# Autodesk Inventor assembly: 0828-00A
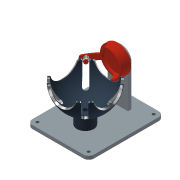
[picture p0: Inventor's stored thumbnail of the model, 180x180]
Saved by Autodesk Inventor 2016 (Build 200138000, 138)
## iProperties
Shininess: 64.0
Length Units: 11269
Angle Units: 11279
Time Units: 11290
Mass Units: 11283
Length Display Precision: 3
Angle Display Precision: 2
Compacted: True
Created: 2003-08
Part Number: 0828-00A
Document SubType Name: Assembly
Designer: 40664
Manufacturer: Standard
Standards Organization: Custom
Density: 0.0
Volumn: 0.0
Area: 0.0
PropertySet Name: Model Information
Control State: 0
Master: False
Checked Out: False
Author: 40664
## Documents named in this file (7)
- G:\InventorKurs\Geneva2\0828-00A.iam
- G:\InventorKurs\Geneva2\Geneva.ipt
- G:\InventorKurs\Geneva2\Plate.ipt
- G:\InventorKurs\Geneva2\0828-01P.ipt
- G:\InventorKurs\Geneva2\0828-02P.ipt
- G:\InventorKurs\Geneva2\Pin.ipt
- G:\InventorKurs\Geneva2\DIN471.ipt
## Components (6 placed, 6 different names)
1. Plate:1 — Flush:1, Insert:1, Mate:1, Mate:2, Flush:2, Angle:1, Angle:5
2. Geneva:1 — Insert:1, Angle:1
3. 0828-01P:1 — Mate:1, Mate:2, Insert:2, Flush:2
4. 0828-02P:1 — Insert:2, Insert:3, Angle:5
5. DIN 471  <= 9mm 8 x 0.8:1 — Insert:4
6. Pin:1 — Insert:3, Insert:4
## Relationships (10: Insert 4, Flush 2, Mate 2, Angle 2)
- Flush:1: Plate:1
- Insert:1: Plate:1 ↔ Geneva:1
- Mate:1: Plate:1 ↔ 0828-01P:1
- Mate:2: Plate:1 ↔ 0828-01P:1
- Insert:2: 0828-01P:1 ↔ 0828-02P:1
- Flush:2: Plate:1 ↔ 0828-01P:1
- Angle:1: Plate:1 ↔ Geneva:1
- Insert:3: 0828-02P:1 ↔ Pin:1
- Angle:5: Plate:1 ↔ 0828-02P:1
- Insert:4: DIN 471  <= 9mm 8 x 0.8:1 ↔ Pin:1
